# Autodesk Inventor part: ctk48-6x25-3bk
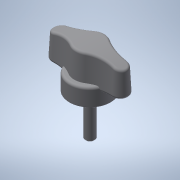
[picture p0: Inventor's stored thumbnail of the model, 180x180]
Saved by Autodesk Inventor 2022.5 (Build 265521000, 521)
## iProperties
Created: 2016-12
Part Number: ctk48-6x25-3bk
Material: 一般
Document SubType Name: Modeling
Designer: imaocorp
Density: 1 g/cm^3
Appearance: 既定
Author: imaocorp
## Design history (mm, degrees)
node "ctk48-6x25-3bk.x_t1"
node "ctk48-6x25-3bk"
node "Base1"
